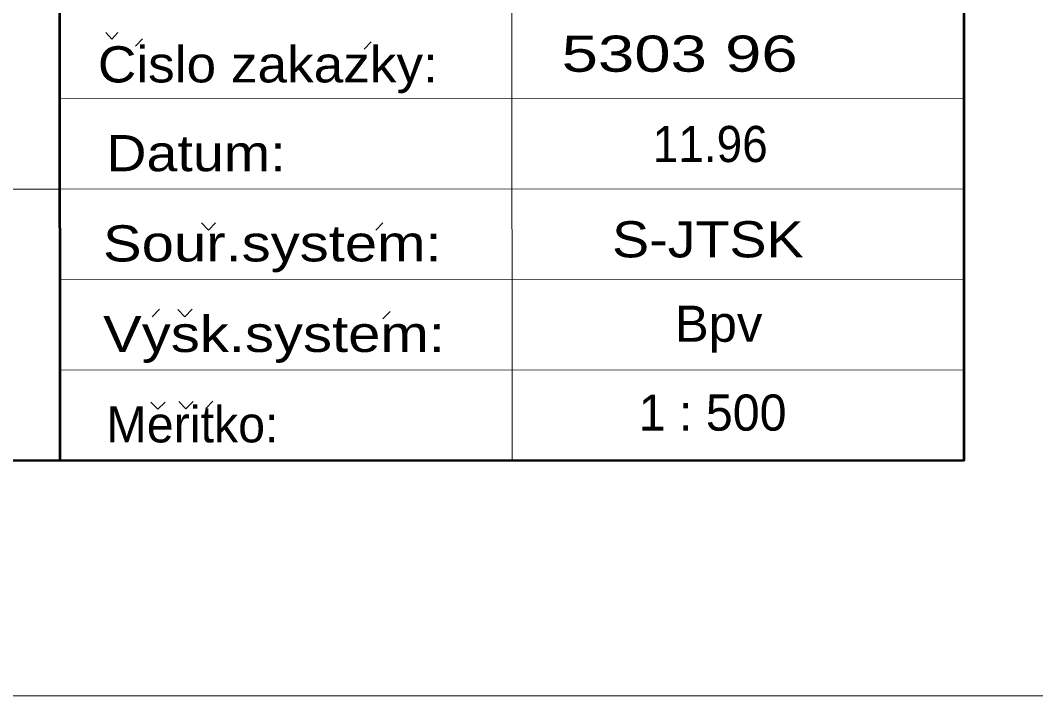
# Model space of a CAD drawing. Extents: x -670514 to -669423, y -1130798 to -1130123.
# Drawn here: x -670470.18 to -670447.72, y -1130676.76 to -1130661.82 of the extents above; entities that cross this region are included whole.
import ezdxf
from ezdxf.enums import TextEntityAlignment as Align

# ---------------------------------------------------------------- set-up
doc = ezdxf.new("R2010")
doc.units = 0
doc.header["$LTSCALE"] = 0.24
doc.layers.add('60', color=7, linetype='Continuous', lineweight=13)
doc.layers.add('61', color=7, linetype='Continuous', lineweight=13)

msp = doc.modelspace()

# ---------------------------------------------------------------- linework, layer by layer
at = {"layer": '60'}
msp.add_lwpolyline([(-670513.627, -1130676.756), (-670103.627, -1130676.756), (-670103.627, -1130389.756), (-670513.627, -1130389.756)], close=True, dxfattribs=at)
at = {"layer": '61', "lineweight": 53}
msp.add_line((-670469.296, -1130671.552), (-670469.301, -1130651.55), dxfattribs=at)
at = {"layer": '61'}
for p, q in [((-670459.303, -1130657.547), (-670459.299, -1130671.55)), ((-670468.286, -1130662.083), (-670468.153, -1130662.234)), ((-670468.021, -1130662.085), (-670468.153, -1130662.234)), ((-670467.629, -1130662.39), (-670467.473, -1130662.224)), ((-670462.57, -1130662.455), (-670462.413, -1130662.295)), ((-670469.3, -1130663.551), (-670449.301, -1130663.548)), ((-670509.3, -1130665.563), (-670469.302, -1130665.553)), ((-670469.302, -1130665.553), (-670449.299, -1130665.545)), ((-670462.312, -1130666.459), (-670462.156, -1130666.295)), ((-670469.297, -1130667.551), (-670449.298, -1130667.544)), ((-670467.255, -1130668.372), (-670467.098, -1130668.206)), ((-670462.154, -1130668.419), (-670461.994, -1130668.257)), ((-670469.297, -1130669.553), (-670449.298, -1130669.549)), ((-670466.069, -1130670.406), (-670465.913, -1130670.239))]:
    msp.add_line(p, q, dxfattribs=at)
at = {"layer": '61', "lineweight": 53}
msp.add_lwpolyline([(-670509.297, -1130671.564), (-670449.3, -1130671.545), (-670449.301, -1130651.548), (-670509.3, -1130651.56)], close=True, dxfattribs=at)
at = {"layer": '61'}
for points in [[(-670465.854, -1130666.298), (-670466.01, -1130666.462), (-670466.169, -1130666.294)], [(-670466.375, -1130668.204), (-670466.533, -1130668.374), (-670466.689, -1130668.21)], [(-670466.973, -1130670.261), (-670467.131, -1130670.421), (-670467.287, -1130670.261)], [(-670466.355, -1130670.246), (-670466.515, -1130670.407), (-670466.672, -1130670.246)]]:
    msp.add_lwpolyline(points, dxfattribs=at)

# ---------------------------------------------------------------- texts
for s, rotation, width, p in [('5303 96', 0.015, 1.35, (-670458.201, -1130662.955)), ('Cislo zakazky:', 0.014, 1.1, (-670468.459, -1130663.191)), ('11.96', 0.015, 0.95, (-670456.186, -1130664.953)), ('Datum:', 0.014, 1.15, (-670468.272, -1130665.155)), ('Sour.system:', 0.014, 1.2, (-670468.347, -1130667.151)), ('Vysk.system:', 0.014, 1.2, (-670468.344, -1130669.154))]:
    msp.add_text(s, height=0.8, rotation=rotation, dxfattribs=dict(at, width=width)).set_placement(p)
for s, width, p in [('S-JTSK', 1.15, (-670454.9671, -1130667.0605)), ('Bpv', 1.05, (-670454.7291, -1130668.9278))]:
    msp.add_text(s, height=0.8, rotation=0.014, dxfattribs=dict(at, width=width)).set_placement(p, align=Align.CENTER)
msp.add_text('1 : 500', height=0.8, rotation=0.014, dxfattribs=at).set_placement((-670454.8621, -1130670.8935), align=Align.CENTER)
msp.add_text('Meritko:', height=0.8, rotation=0.014, dxfattribs=at).set_placement((-670468.269, -1130671.154))

doc.saveas('drawing.dxf')
